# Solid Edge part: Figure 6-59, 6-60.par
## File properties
Author: Ashutosh-CADCIM
Template: iso metric part.par
Last saved by: Ashutosh-CADCIM
Revision: 1
Application: Solid Edge
Accuracy: 0.990
Username: Ashutosh-CADCIM
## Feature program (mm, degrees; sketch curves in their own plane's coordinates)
sketch for "unnamed Protrusion 1" plane through (0, 0, 0) normal (0, 0, 1) x-axis (1, 0, 0)
  line (-50, -30) -> (50, -30)
  line (50, -30) -> (50, 30)
  line (50, 30) -> (-50, 30)
  line (-50, 30) -> (-50, -30)
extrude "unnamed Protrusion 1" add finite 12 symmetric
sketch for "unnamed Cutout 1" plane through (0, 0, 6) normal (0, 0, 1) x-axis (0, 1, 0)
  line (1.2145, 40.5976) -> (-11.6241, 40.5976)
  line (-11.6241, 40.5976) -> (-11.6241, 34.6988)
  line (-11.6241, 34.6988) -> (1.2145, 34.6988)
  line (1.2145, 34.6988) -> (1.2145, 40.5976)
extrude "unnamed Cutout 1" cut through along -normal
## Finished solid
Body 1: solid body, 10 faces, 24 edges, 16 vertices.
  Faces by surface: plane 10
  Edges by curve: line 24
Bounding box of the edges (mm): 100.000 x 60.000 x 12.000, from (-50, -30, -6) to (50, 30, 6).
Planar faces by outward normal: +x 2, +y 2, +z 1, -x 2, -y 2, -z 1
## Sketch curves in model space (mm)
spline (-40.5976, 1.2145, 6) -> (9.7248, 16.3852, 6) -> (40.3886, -3.223, 6)
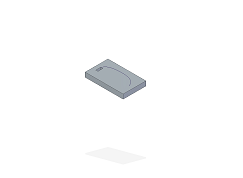
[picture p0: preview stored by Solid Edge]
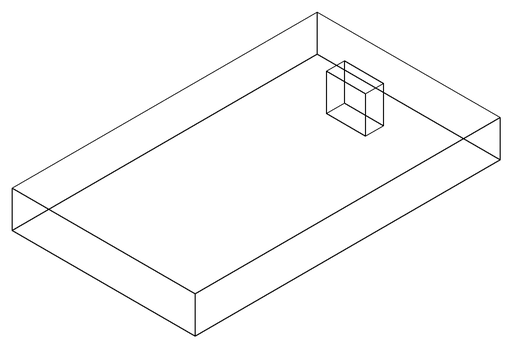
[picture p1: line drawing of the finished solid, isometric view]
